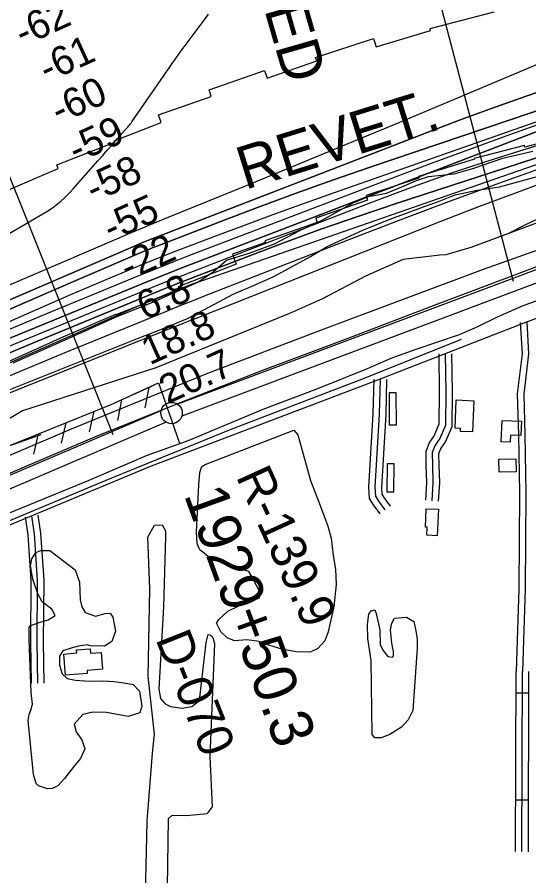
# Model space of a CAD drawing. Extents: x 3508733 to 3546731, y 546897 to 572481.
# Drawn here: x 3516531 to 3517725, y 561711 to 563717 of the extents above; entities that cross this region are included whole.
import ezdxf

# ---------------------------------------------------------------- set-up
doc = ezdxf.new("R2010")
doc.units = 0
for name, color, linetype in [('V-BLDG-OTLN', 7, 'Continuous'), ('V-CHAN-NAID', 7, 'Continuous'), ('V-FLOD-BASE', 7, 'Continuous'), ('V-LEVE-TOET', 7, 'Continuous'), ('V-RIVR-EDGE', 7, 'Continuous'), ('V-RIVR-RANG', 7, 'Continuous'), ('V-RIVR-RANG-IDEN', 7, 'Continuous'), ('V-ROAD-CNTR', 7, 'Continuous'), ('V-RRAP-FSHR', 7, 'Continuous'), ('V-RRAP-RVMT', 7, 'Continuous'), ('V-RRAP-RVMT-IDEN', 7, 'Continuous'), ('V-SITE-VEGE', 7, 'Continuous'), ('V-SURV-IDEN', 7, 'Continuous'), ('V-SURV-LINE', 7, 'Continuous'), ('V-TOPO-DPTH', 7, 'Continuous'), ('V-TOPO-MAJR', 7, 'Continuous'), ('V-TOPO-MINR', 7, 'Continuous'), ('V-TOPO-SHOR', 7, 'Continuous'), ('V-TOPO-WATR', 7, 'Continuous')]:
    doc.layers.add(name, color=color, linetype=linetype)

msp = doc.modelspace()

# ---------------------------------------------------------------- linework, layer by layer
at = {"layer": 'V-BLDG-OTLN'}
for points in [[(3517414.5, 562840.3), (3517415, 562763.7), (3517400, 562763.7), (3517399.5, 562840.2)], [(3517555.5, 562822.6), (3517596.5, 562820.8), (3517593.4, 562748.1), (3517565.2, 562749.3), (3517565.5, 562756.3), (3517552.7, 562756.9)], [(3517662.6, 562775), (3517707.6, 562772.9), (3517706.1, 562739.7), (3517682.2, 562740.8), (3517681.4, 562723.7), (3517660.3, 562724.7)], [(3517654.9, 562684.3), (3517694.7, 562684.9), (3517695.2, 562655), (3517655.4, 562654.4)], [(3517409.6, 562674.2), (3517409.2, 562607.1), (3517394.5, 562607.2), (3517394.9, 562674.2)], [(3517513.6, 562567.5), (3517510.8, 562505.5), (3517486.6, 562506.6), (3517487.5, 562525.4), (3517483.4, 562525.6), (3517485.3, 562568.7)], [(3516730.3, 562194), (3516694, 562191.1), (3516694.6, 562184.1), (3516644, 562180), (3516639.9, 562229.4), (3516670.3, 562231.9), (3516669.7, 562239.1), (3516701.4, 562241.7), (3516702.3, 562231.4), (3516727, 562233.3)]]:
    msp.add_lwpolyline(points, close=True, dxfattribs=at)
at = {"layer": 'V-FLOD-BASE'}
msp.add_lwpolyline([(3516367.4, 562586.1), (3516532.1, 562659.6), (3516712.1, 562736.2), (3516909.8, 562815.7), (3517101.6, 562891.8), (3517297, 562964.8), (3517512.3, 563046.9), (3517727.1, 563127.8), (3517876.6, 563185.2), (3518022, 563233.3), (3518218.5, 563309.9), (3518287.9, 563329.2), (3518314.5, 563331.1), (3518407, 563339.3), (3518555, 563347.8), (3518668.7, 563357.3)], dxfattribs=at)
at = {"layer": 'V-LEVE-TOET'}
for points in [[(3516377.5, 562635.5), (3516658.1, 562755.1), (3516975.8, 562885.5), (3517241.2, 562986.1), (3517618.9, 563128.1), (3517997.9, 563263), (3518268, 563364.2), (3518279.2, 563366.7), (3518410.7, 563375.7), (3518673, 563392), (3518788.5, 563399.7), (3518987.4, 563408.2)], [(3516496.2, 562552), (3516699.2, 562635.7), (3516832.7, 562693.1), (3516932.2, 562728.5), (3517105.2, 562800.9), (3517232.8, 562849.4), (3517348.2, 562896.1), (3517403.5, 562920), (3517461.7, 562941.5), (3517562.9, 562975.7), (3517605.9, 562994.3), (3517651.8, 563016.4), (3517710, 563042.1), (3517850, 563093.6)]]:
    msp.add_lwpolyline(points, dxfattribs=at)
at = {"layer": 'V-RIVR-EDGE'}
msp.add_lwpolyline([(3516522.1, 562909.3), (3516641.7, 562961.9), (3516760.1, 563016.2), (3516849, 563051.4), (3516952.4, 563098), (3516987.9, 563121.9), (3517019.2, 563149.4), (3517037.2, 563154.2), (3517072, 563165.5), (3517131.5, 563187.6), (3517190.4, 563218.7), (3517240.9, 563241.4), (3517314.9, 563282.6), (3517350.9, 563297.5), (3517392.4, 563305.2), (3517428.4, 563320.7), (3517462.7, 563335.1), (3517490.9, 563344.6), (3517550.4, 563350.4), (3517594.2, 563362.9), (3517663.9, 563387.4), (3517733.6, 563404)], dxfattribs=at)
at = {"layer": 'V-RIVR-RANG'}
for p, q in [((3517689, 563099.2), (3517480.5, 563893.3)), ((3516755.3, 562741.5), (3516442.4, 563521))]:
    msp.add_line(p, q, dxfattribs=at)
at = {"layer": 'V-ROAD-CNTR'}
for p, q in [((3517723.8, 562138.2), (3517693.8, 562138.3)), ((3517723.2, 561888.2), (3517693.2, 561888.3))]:
    msp.add_line(p, q, dxfattribs=at)
for points in [[(3518185, 563177), (3518070.5, 563139.1), (3517881.5, 563064.1), (3517716.5, 563003.6), (3517371.7, 562868.5), (3516843.7, 562668.3), (3516559.9, 562549.6), (3516307, 562444.5), (3515895.5, 562264.3), (3515695.8, 562177), (3515359.6, 562027.6), (3515169.1, 561950.3), (3515006.8, 561875.8), (3514680.2, 561669.4), (3514432.2, 561519.5)], [(3517704.8, 563003.9), (3517709.2, 562930.7), (3517697.6, 562837.1), (3517700.5, 562741.1), (3517703, 562605.9), (3517701.2, 562381.8), (3517695, 562188.7)], [(3517719.8, 563004.8), (3517724.2, 562930.2), (3517712.7, 562836.4), (3517715.5, 562741.5), (3517718, 562606), (3517716.1, 562381.5), (3517710, 562188.2)], [(3517514.4, 562930.1), (3517515.8, 562840.9), (3517515, 562766.1), (3517503.8, 562739.9), (3517493.1, 562724.3), (3517484, 562702.4), (3517484.7, 562669.4), (3517485.9, 562629.9), (3517483.3, 562588.3)], [(3517529.4, 562930.3), (3517530.8, 562840.9), (3517530, 562762.9), (3517517, 562732.7), (3517506.3, 562717.1), (3517499.1, 562699.6), (3517499.7, 562669.7), (3517500.9, 562629.7), (3517498.3, 562587.4)], [(3517544.4, 562930.6), (3517545.8, 562841), (3517545, 562759.8), (3517530.2, 562725.4), (3517519.6, 562709.9), (3517514.1, 562696.8), (3517514.7, 562670.1), (3517515.9, 562629.5), (3517513.2, 562586.4)], [(3517363, 562871.4), (3517360.7, 562790.1), (3517350.7, 562618.7), (3517352, 562592.8), (3517361.5, 562577.9), (3517376.7, 562557.1)], [(3517378, 562871), (3517375.7, 562789.5), (3517365.7, 562618.7), (3517366.8, 562597.6), (3517373.9, 562586.4), (3517388.9, 562565.9)], [(3517393, 562870.6), (3517390.7, 562788.8), (3517380.7, 562618.6), (3517381.6, 562602.3), (3517386.3, 562594.8), (3517401, 562574.8)], [(3516549.5, 562549.1), (3516556.1, 562508), (3516563.1, 562401.3), (3516562, 562256.7), (3516563.6, 562161.1)], [(3516564.3, 562551.5), (3516571, 562509.7), (3516578.1, 562401.8), (3516577, 562256.7), (3516578.6, 562161.3)], [(3516579.1, 562553.9), (3516585.9, 562511.3), (3516593.1, 562402.2), (3516592, 562256.8), (3516593.6, 562161.6)], [(3517694, 562188.3), (3517692.9, 561767.9)], [(3517709, 562188.3), (3517707.9, 561767.9)], [(3517724, 562188.2), (3517722.9, 561767.8)]]:
    msp.add_lwpolyline(points, dxfattribs=at)
at = {"layer": 'V-RRAP-FSHR'}
for p, q in [((3516838, 562852), (3516829.1, 562803.9)), ((3516774.3, 562822.9), (3516765.4, 562774.9)), ((3516709.9, 562795.7), (3516698.9, 562748.1)), ((3516644.9, 562769.5), (3516634, 562721.9)), ((3516580, 562743.2), (3516569.1, 562695.7))]:
    msp.add_line(p, q, dxfattribs=at)
for points in [[(3512861.8, 560815), (3513646.8, 561263.9), (3514508.5, 561793.8), (3515097.9, 562097.5), (3515670.4, 562357.8), (3516323, 562639.4), (3516750.7, 562812.2), (3516861, 562862.4), (3516910.1, 562722)], [(3515986.1, 562494.1), (3516323, 562639.4), (3516750.7, 562812.2), (3516851.8, 562858.2)]]:
    msp.add_lwpolyline(points, dxfattribs=at)
at = {"layer": 'V-RRAP-RVMT'}
for p, q in [((3517494.2, 563690.2), (3517643.6, 563729)), ((3517368.7, 563646.9), (3517495.4, 563685.7)), ((3517495.4, 563685.7), (3517494.2, 563690.2)), ((3517227.2, 563622.7), (3517362.2, 563666.7)), ((3517362.2, 563666.7), (3517368.7, 563646.9)), ((3517230, 563614.2), (3517227.2, 563622.7)), ((3517114.3, 563574), (3517230, 563614.2)), ((3516978.7, 563546.9), (3517108, 563591.8)), ((3517108, 563591.8), (3517114.3, 563574)), ((3516984, 563531.5), (3516978.7, 563546.9)), ((3516860.9, 563488.7), (3516984, 563531.5)), ((3516867.2, 563470.5), (3516860.9, 563488.7)), ((3516757.5, 563427.6), (3516867.2, 563470.5)), ((3517866.5, 563452.4), (3517715.6, 563413.3)), ((3516623.8, 563371.5), (3516758.7, 563424.5)), ((3516758.7, 563424.5), (3516757.5, 563427.6)), ((3517714.6, 563417.1), (3517597.4, 563386.7)), ((3517715.6, 563413.3), (3517714.6, 563417.1)), ((3517598, 563385), (3517466.9, 563344.8)), ((3517597.4, 563386.7), (3517598, 563385)), ((3516505.1, 563310.8), (3516627, 563363.5)), ((3516627, 563363.5), (3516623.8, 563371.5)), ((3517466.9, 563344.8), (3517468.4, 563340.4)), ((3517468.4, 563340.4), (3517344.9, 563300.2)), ((3517348.6, 563289.3), (3517227.6, 563247.2)), ((3517344.9, 563300.2), (3517348.6, 563289.3)), ((3517227.6, 563247.2), (3517231.2, 563237.1)), ((3517231.2, 563237.1), (3517108.9, 563194.6)), ((3517110.4, 563190.3), (3517033, 563163.4)), ((3517108.9, 563194.6), (3517110.4, 563190.3)), ((3517033, 563163.4), (3517042.2, 563140.1)), ((3517042.2, 563140.1), (3516907, 563087)), ((3516907, 563087), (3516909.9, 563079.8)), ((3516909.9, 563079.8), (3516761.1, 563021.5)), ((3516760.8, 563022.5), (3516639.4, 562969.9)), ((3516761.1, 563021.5), (3516760.8, 563022.5)), ((3516639.3, 562970.3), (3516510.4, 562911.8)), ((3516639.4, 562969.9), (3516639.3, 562970.3))]:
    msp.add_line(p, q, dxfattribs=at)
at = {"layer": 'V-SITE-VEGE'}
for points in [[(3516453, 562822.8), (3516819.6, 562969.3), (3516866.3, 562986.8), (3516928.3, 563012.6), (3516991.4, 563046.1), (3517035, 563070), (3517082.3, 563089.8), (3517128.3, 563110.2), (3517165.5, 563130.5), (3517215, 563157.4), (3517253.9, 563180.7), (3517337.2, 563219.1), (3517402.7, 563245.5), (3517442.8, 563260.5), (3517483, 563275), (3517513.7, 563286.4), (3517552.7, 563302), (3517604.1, 563312.4), (3517656.1, 563320.4), (3517863.5, 563377.2)], [(3517840.4, 563271.7), (3517589.5, 563178.6), (3517531, 563161.6), (3517516.8, 563161), (3517431.6, 563150.4), (3517343.7, 563112), (3517243.4, 563058.8), (3517166.7, 563024.6), (3516854.4, 562897.3), (3516543.7, 562797.3), (3516450, 562742.3)], [(3516822.8, 561321.3), (3516834.5, 561838.6), (3516835.1, 561849.3), (3516846.6, 561997.8), (3516851.1, 562042.3), (3516836.7, 562176.5), (3516840.8, 562381.9), (3516836, 562502.5), (3516851.8, 562530.4), (3516869.5, 562531.1), (3516877.3, 562517), (3516876.8, 562502.8), (3516872.4, 562339.4), (3516861.7, 562147.6), (3516865.4, 562125.2), (3516876.1, 562112.8), (3516888.6, 562107), (3516915.8, 562103), (3516938.3, 562106.7), (3516956.6, 562121), (3516972.3, 562256), (3516976.4, 562274.9), (3516981.7, 562273.2), (3516987.7, 562267.9), (3516991.3, 562253.7), (3516980.4, 561989.8), (3516985.8, 561872.6), (3516975.8, 561859), (3516974.1, 561856), (3516926.2, 561851.6), (3516891.8, 561852.5), (3516883, 561844.8), (3516879.8, 561577.9)]]:
    msp.add_lwpolyline(points, dxfattribs=at)
for points in [[(3516969.3, 562672), (3517176.6, 562751.9), (3517185.5, 562741.3), (3517215.7, 562634.4), (3517234.3, 562586.5), (3517247.6, 562551.1), (3517255.4, 562528.1), (3517263.2, 562499.7), (3517268.2, 562459.5), (3517273.7, 562427.6), (3517275.1, 562391.5), (3517270.1, 562340.6), (3517256.2, 562281.3), (3517248.7, 562260), (3517232.2, 562242.1), (3517214.5, 562233.7), (3517181.9, 562234.1), (3517148.8, 562240.5), (3517118.5, 562250.3), (3517095.4, 562258.5), (3517067, 562262.5), (3517038, 562260.5), (3517020.8, 562266.9), (3517005.9, 562281), (3516996.3, 562301.1), (3517001.6, 562310), (3517022.8, 562329.7), (3517048.2, 562341.6), (3517050.5, 562345.8), (3517075.9, 562352.5), (3517096, 562360.3), (3517096.5, 562376.2), (3517076.8, 562412.8), (3517071.4, 562421.7), (3517057.1, 562426.9), (3517005, 562447.9), (3516980.1, 562454.9), (3516957.5, 562472.5), (3516950.9, 562486.6), (3516949.5, 562513.9), (3516954.8, 562624.5), (3516957, 562653.6), (3516962.2, 562667.2)], [(3516610.1, 562468.7), (3516666, 562425.8), (3516676.8, 562396.9), (3516678.3, 562356.1), (3516681.9, 562339.5), (3516689.7, 562326.5), (3516714, 562317.8), (3516736.4, 562323.8), (3516747.7, 562325.1), (3516754.2, 562315.1), (3516760.3, 562282.6), (3516752.2, 562258.3), (3516735.1, 562247.5), (3516701.4, 562248.5), (3516694.3, 562250.8), (3516674.1, 562247.7), (3516659.4, 562243.5), (3516637.5, 562236.9), (3516629.9, 562224.4), (3516630, 562203.1), (3516636.1, 562183), (3516648, 562172.4), (3516667.5, 562168.4), (3516698.3, 562165.6), (3516731.4, 562166.4), (3516756.3, 562165.4), (3516780.6, 562162), (3516801.9, 562158), (3516816.2, 562142.6), (3516821.7, 562107.2), (3516817.1, 562092.4), (3516789.9, 562083.3), (3516739.6, 562092.5), (3516707.6, 562093.5), (3516684.5, 562088), (3516664, 562065.4), (3516668.8, 562047.7), (3516681.9, 562028.8), (3516689.2, 562007.6), (3516679.2, 561985.6), (3516663.4, 561966.6), (3516641.6, 561938.7), (3516625.8, 561921.4), (3516613.4, 561915.4), (3516601.5, 561914.2), (3516580.8, 561921.7), (3516575.4, 561927), (3516569.4, 561948.3), (3516556.8, 562074.3), (3516559.1, 562087.9), (3516563.2, 562098.6), (3516566.6, 562112.2), (3516563.5, 562139.4), (3516560, 562241.7), (3516559.2, 562265.4), (3516559.1, 562291.5), (3516560.3, 562295), (3516582.1, 562302.8), (3516603.4, 562309.5), (3516619.9, 562319.6), (3516612.1, 562333.8), (3516589.5, 562351.4), (3516579.4, 562369.7), (3516567.3, 562403.9), (3516562.4, 562435.3), (3516565.3, 562451.8), (3516574.6, 562466.7), (3516586.5, 562470.9), (3516607.2, 562471)], [(3517464.2, 562242.9), (3517454.4, 562097.8), (3517443.2, 562075.9), (3517427.4, 562058.6), (3517400.2, 562041.3), (3517380.2, 562033.5), (3517365.4, 562034), (3517359.4, 562041.1), (3517356.6, 562214.4), (3517349.2, 562265.9), (3517348.4, 562298.4), (3517351.3, 562322.1), (3517356.5, 562330.4), (3517365.4, 562332.8), (3517368.4, 562324), (3517376.9, 562286.2), (3517377.7, 562251.3), (3517383.7, 562238.3), (3517395.6, 562223.5), (3517405.7, 562221.8), (3517408.6, 562225.4), (3517409.2, 562234.9), (3517404.9, 562255), (3517401.8, 562285.7), (3517405.2, 562301.7), (3517411.1, 562313), (3517439.5, 562315.5), (3517456.7, 562305), (3517461, 562283.7), (3517464, 562264.2)]]:
    msp.add_lwpolyline(points, close=True, dxfattribs=at)
at = {"layer": 'V-SURV-LINE'}
for points in [[(3516904.6, 562813.1), (3518247.6, 563317.2)], [(3518258.1, 563289.1), (3516915.2, 562785)], [(3514999.5, 561999.3), (3516866.9, 562798)], [(3516878.7, 562770.4), (3515011.3, 561971.7)]]:
    msp.add_lwpolyline(points, dxfattribs=at)
msp.add_circle((3516891.2, 562792), 25, dxfattribs=at)
at = {"layer": 'V-TOPO-DPTH'}
for points in [[(3518316.9, 563726.1), (3518265.3, 563708.1), (3518213.5, 563690.8), (3518161.5, 563674.1), (3518128.6, 563663.8), (3518092.9, 563652.7), (3518057.2, 563641.6), (3518021.4, 563630.7), (3517985.7, 563619.9), (3517949.9, 563609), (3517914.2, 563597.9), (3517878.7, 563586.3), (3517843.2, 563574.6), (3517774.5, 563551.4), (3517704.9, 563527.4), (3517635.6, 563502.8), (3517566.5, 563477.3), (3517497.7, 563451.2), (3516869.9, 563208.5), (3516853.8, 563202.2), (3516837.8, 563195.8), (3516821.9, 563189.2), (3516806, 563182.4), (3516171.7, 562909.3)], [(3518316.9, 563726.1), (3518265.3, 563708.1), (3518213.5, 563690.8), (3518161.5, 563674.1), (3518128.6, 563663.8), (3518092.9, 563652.7), (3518057.2, 563641.6), (3518021.4, 563630.7), (3517985.7, 563619.9), (3517949.9, 563609), (3517914.2, 563597.9), (3517878.7, 563586.3), (3517843.2, 563574.6), (3517774.5, 563551.4), (3517704.9, 563527.4), (3517635.6, 563502.8), (3517566.5, 563477.3), (3517497.7, 563451.2), (3516869.9, 563208.5), (3516853.8, 563202.2), (3516837.8, 563195.8), (3516821.9, 563189.2), (3516806, 563182.4), (3516171.7, 562909.3)], [(3518502, 563727.2), (3518405.7, 563700.1), (3518309.5, 563672.7), (3518213.4, 563644.8), (3518117.4, 563616.6), (3517958.8, 563569.5), (3517942.2, 563564.4), (3517925.7, 563559.3), (3517909.2, 563553.9), (3517892.7, 563548.5), (3517351.9, 563365.3), (3517266.9, 563335.9), (3517182.2, 563305.8), (3517097.9, 563274.6), (3517013.8, 563242.7), (3516859.4, 563182.9), (3516852.7, 563180.3), (3516846.1, 563177.6), (3516839.4, 563174.9), (3516832.8, 563172.1), (3516667.8, 563101.4), (3516578.8, 563063), (3516489.9, 563024.3)], [(3516489.9, 563024.3), (3516578.8, 563063), (3516667.8, 563101.4), (3516832.8, 563172.1), (3516839.4, 563174.9), (3516846.1, 563177.6), (3516852.7, 563180.3), (3516859.4, 563182.9), (3517013.8, 563242.7), (3517097.9, 563274.6), (3517182.2, 563305.8), (3517266.9, 563335.9), (3517351.9, 563365.3), (3517892.7, 563548.5), (3517909.2, 563553.9), (3517925.7, 563559.3), (3517942.2, 563564.4), (3517958.8, 563569.5), (3518117.4, 563616.6), (3518213.4, 563644.8), (3518309.5, 563672.7), (3518405.7, 563700.1), (3518502, 563727.2)], [(3515784.7, 562679.8), (3516548.2, 563021.4), (3516599.4, 563044.1), (3516650.7, 563066.5), (3516702.1, 563088.5), (3516753.7, 563110.3), (3516776, 563119.7), (3516816.6, 563136.4), (3516857.2, 563152.9), (3516898.1, 563169), (3516939.1, 563184.8), (3516994.6, 563205.9), (3517063.5, 563231.8), (3517132.5, 563257.3), (3517201.7, 563282.3), (3517271, 563306.9), (3517919.4, 563534.5)], [(3515784.7, 562679.8), (3516548.2, 563021.4), (3516599.4, 563044.1), (3516650.7, 563066.5), (3516702.1, 563088.5), (3516753.7, 563110.3), (3516776, 563119.7), (3516816.6, 563136.4), (3516857.2, 563152.9), (3516898.1, 563169), (3516939.1, 563184.8), (3516994.6, 563205.9), (3517063.5, 563231.8), (3517132.5, 563257.3), (3517201.7, 563282.3), (3517271, 563306.9), (3517919.4, 563534.5)], [(3517852.9, 563491.9), (3516917.2, 563131.9), (3516895.8, 563123.6), (3516874.4, 563115.2), (3516853.1, 563106.6), (3516831.8, 563098), (3516198.7, 562837.9)], [(3516198.7, 562837.9), (3516831.8, 563098), (3516853.1, 563106.6), (3516874.4, 563115.2), (3516895.8, 563123.6), (3516917.2, 563131.9), (3517852.9, 563491.9)], [(3517929.1, 563448.7), (3517417.4, 563281.9), (3517328.1, 563252), (3517239.1, 563221.1), (3517150.7, 563188.8), (3517062.6, 563155.5), (3516901.3, 563093.1), (3516894.1, 563090.3), (3516887, 563087.5), (3516879.9, 563084.6), (3516872.8, 563081.7), (3516574.9, 562958.6), (3516442.2, 562903.3)], [(3517929.1, 563448.7), (3517417.4, 563281.9), (3517328.1, 563252), (3517239.1, 563221.1), (3517150.7, 563188.8), (3517062.6, 563155.5), (3516901.3, 563093.1), (3516894.1, 563090.3), (3516887, 563087.5), (3516879.9, 563084.6), (3516872.8, 563081.7), (3516574.9, 562958.6), (3516442.2, 562903.3)], [(3516511.2, 562878.4), (3516643.2, 562933.2), (3516847.5, 563017.1), (3516877.6, 563029.4), (3516907.8, 563041.6), (3516938.1, 563053.6), (3516968.4, 563065.5), (3517337.7, 563209.9), (3517441, 563249.7), (3517544.6, 563288.8), (3517648.5, 563326.8), (3517752.8, 563364.2)]]:
    msp.add_lwpolyline(points, dxfattribs=at)
at = {"layer": 'V-TOPO-MAJR'}
msp.add_lwpolyline([(3516373.4, 563031.9), (3516763.5, 563199), (3516794, 563211.9), (3516824.6, 563224.8), (3516855.2, 563237.5), (3516885.9, 563250.2), (3517062.1, 563322.1), (3517180.8, 563370.9), (3517299.5, 563419.8), (3517417.9, 563469.2), (3517536.3, 563518.8), (3517848.3, 563650), (3517870.7, 563659.4), (3517893.2, 563668.7), (3517915.8, 563678), (3517938.3, 563687.1), (3518015.9, 563718.3)], dxfattribs=at)
at = {"layer": 'V-TOPO-MINR'}
for points in [[(3516171.7, 562909.3), (3516806, 563182.4), (3516821.9, 563189.2), (3516837.8, 563195.8), (3516853.8, 563202.2), (3516869.9, 563208.5), (3517497.7, 563451.2), (3517566.5, 563477.3), (3517635.6, 563502.8), (3517704.9, 563527.4), (3517774.5, 563551.4), (3517843.2, 563574.6), (3517878.7, 563586.3), (3517914.2, 563597.9), (3517949.9, 563609), (3517985.7, 563619.9), (3518021.4, 563630.7), (3518057.2, 563641.6), (3518092.9, 563652.7), (3518128.6, 563663.8), (3518161.5, 563674.1), (3518213.5, 563690.8), (3518265.3, 563708.1), (3518316.9, 563726.1)], [(3516372.9, 563130.4), (3516600.1, 563263.1), (3516608.7, 563268.5), (3516617.1, 563274.2), (3516625.2, 563280.3), (3516633.1, 563286.8), (3516640.6, 563293.6), (3516648, 563300.7), (3516655.1, 563308), (3516662, 563315.5), (3516719.6, 563380.9), (3516730.9, 563393.7), (3516742.1, 563406.5), (3516753.4, 563419.3), (3516764.6, 563432.1), (3516783.2, 563453.1), (3516785.1, 563455.4), (3516787.1, 563457.7), (3516789.1, 563459.9), (3516791.1, 563462.2), (3516793, 563464.5), (3516794.9, 563466.9), (3516796.7, 563469.3), (3516798.4, 563471.8), (3516873.7, 563581.3), (3516878.3, 563588), (3516883, 563594.7), (3516887.6, 563601.5), (3516892.3, 563608.2), (3516897.1, 563614.9), (3516901.8, 563621.5), (3516906.6, 563628.1), (3516911.5, 563634.7), (3516969.4, 563712.3), (3516977.6, 563723.4)], [(3516468.2, 562969), (3516600.6, 563024.5), (3516804.1, 563108.8), (3516835, 563121.4), (3516865.9, 563133.9), (3516896.9, 563146.1), (3516928, 563158.1), (3517411, 563342.9), (3517497.7, 563375.6), (3517584.5, 563407.9), (3517671.6, 563439.5), (3517758.9, 563470.6), (3517928.1, 563530.1), (3517930.9, 563531), (3517933.8, 563531.9), (3517936.6, 563532.7), (3517939.5, 563533.4), (3518825.8, 563738.6)], [(3516489.9, 563024.3), (3516578.8, 563063), (3516667.8, 563101.4), (3516832.8, 563172.1), (3516839.4, 563174.9), (3516846.1, 563177.6), (3516852.7, 563180.3), (3516859.4, 563182.9), (3517013.8, 563242.7), (3517097.9, 563274.6), (3517182.2, 563305.8), (3517266.9, 563335.9), (3517351.9, 563365.3), (3517892.7, 563548.5), (3517909.2, 563553.9), (3517925.7, 563559.3), (3517942.2, 563564.4), (3517958.8, 563569.5), (3518117.4, 563616.6), (3518213.4, 563644.8), (3518309.5, 563672.7), (3518405.7, 563700.1), (3518502, 563727.2)], [(3515784.7, 562679.8), (3516548.2, 563021.4), (3516599.4, 563044.1), (3516650.7, 563066.5), (3516702.1, 563088.5), (3516753.7, 563110.3), (3516776, 563119.7), (3516816.6, 563136.4), (3516857.2, 563152.9), (3516898.1, 563169), (3516939.1, 563184.8), (3516994.6, 563205.9), (3517063.5, 563231.8), (3517132.5, 563257.3), (3517201.7, 563282.3), (3517271, 563306.9), (3517919.4, 563534.5)], [(3516198.7, 562837.9), (3516831.8, 563098), (3516853.1, 563106.6), (3516874.4, 563115.2), (3516895.8, 563123.6), (3516917.2, 563131.9), (3517852.9, 563491.9)], [(3515836.5, 562610.8), (3516785.8, 563030.2), (3516803.5, 563038), (3516821.2, 563045.6), (3516839, 563053.2), (3516856.8, 563060.6), (3516890.6, 563074.7), (3516891.5, 563075.1), (3516894.3, 563076.2), (3516915.2, 563084.2), (3516926.6, 563088.5), (3516938, 563092.8), (3516949.5, 563096.9), (3516960.9, 563101), (3517941.8, 563441.8)], [(3515808.3, 562658.7), (3516854.6, 563088.9), (3516868, 563094.4), (3516881.4, 563099.8), (3516894.8, 563105.1), (3516908.3, 563110.4), (3517358.4, 563284.8), (3517455.6, 563321.1), (3517553.3, 563355.9), (3517651.7, 563388.3), (3517750.7, 563419.2)], [(3516511.2, 562878.4), (3516643.2, 562933.2), (3516847.5, 563017.1), (3516877.6, 563029.4), (3516907.8, 563041.6), (3516938.1, 563053.6), (3516968.4, 563065.5), (3517337.7, 563209.9), (3517441, 563249.7), (3517544.6, 563288.8), (3517648.5, 563326.8), (3517752.8, 563364.2)], [(3515952.9, 562614.6), (3516902.6, 562995.4), (3516913.7, 562999.8), (3516924.8, 563004.3), (3516935.9, 563008.7), (3516946.9, 563013.1), (3517427.5, 563203.9), (3517517.5, 563239.2), (3517607.7, 563274.1), (3517698.2, 563308.2), (3517788.8, 563341.8)], [(3517990.4, 563340.9), (3517987.2, 563339.9), (3517984, 563338.8), (3517880.1, 563300.8), (3517825.5, 563279.6), (3517771.5, 563256.9), (3517718.5, 563232.1), (3517674, 563209.7)], [(3516120, 562576.6), (3516587, 562741.9)]]:
    msp.add_lwpolyline(points, dxfattribs=at)
at = {"layer": 'V-TOPO-SHOR'}
msp.add_lwpolyline([(3517567, 562963.6), (3517338, 562872.1), (3517029.6, 562753.4), (3516737.8, 562634.9), (3516192.8, 562406.3), (3515625.9, 562156.2), (3515170.9, 561961.3), (3515047.8, 561911.9), (3515022.9, 561899.9), (3514850.3, 561797.5), (3514483.3, 561563.4), (3514010.3, 561277.7), (3513615.4, 561047.9)], dxfattribs=at)
at = {"layer": 'V-TOPO-WATR'}
msp.add_lwpolyline([(3516442.2, 562903.3), (3516574.9, 562958.6), (3516872.8, 563081.7), (3516879.9, 563084.6), (3516887, 563087.5), (3516894.1, 563090.3), (3516901.3, 563093.1), (3517062.6, 563155.5), (3517150.7, 563188.8), (3517239.1, 563221.1), (3517328.1, 563252), (3517417.4, 563281.9), (3517929.1, 563448.7)], dxfattribs=at)

# ---------------------------------------------------------------- texts
at = {"layer": 'V-CHAN-NAID'}
msp.add_text('CARGILL-NAGOC OILSEED ', height=100, rotation=286.0935, dxfattribs=at).set_placement((3516680.7, 565212.5))
at = {"layer": 'V-RIVR-RANG'}
for s, rotation, p in [('-62', 24.5643, (3516544.1, 563646.8)), ('-61', 24.5643, (3516600.6, 563562.7)), ('-60', 24.5643, (3516628.5, 563465.5)), ('-59', 24.5643, (3516668.9, 563374)), ('-58', 24.5643, (3516709.5, 563282.6)), ('-55', 24.5643, (3516749.9, 563191.1)), ('-22', 24.5643, (3516789.3, 563099.2)), ('6.8', 24.2783, (3516829.2, 563007.9)), ('18.8', 24.2783, (3516840.2, 562903.2)), ('20.7', 24.2783, (3516881.5, 562812.2))]:
    msp.add_text(s, height=67, rotation=rotation, dxfattribs=at).set_placement(p)
at = {"layer": 'V-RIVR-RANG-IDEN'}
for s, rotation, p in [('R-139.9', 294.4226, (3517040.5, 562644.1)), ('D-070', 291.7313, (3516853, 562264.6))]:
    msp.add_text(s, height=83, rotation=rotation, dxfattribs=at).set_placement(p)
at = {"layer": 'V-RRAP-RVMT-IDEN'}
msp.add_text('REVET.', height=100, rotation=17.2801, dxfattribs=at).set_placement((3517062.4, 563312.9))
at = {"layer": 'V-SURV-IDEN'}
msp.add_text('1929+50.3', height=100, rotation=289.9974, dxfattribs=at).set_placement((3516919.4, 562601.6))

doc.saveas('drawing.dxf')
